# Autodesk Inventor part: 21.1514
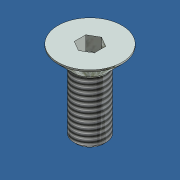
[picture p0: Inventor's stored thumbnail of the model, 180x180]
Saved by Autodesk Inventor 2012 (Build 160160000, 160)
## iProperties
Created: 2006-12
Part Number: 21.1514
Material: Steel, Mild
Description: M8x20 C'SUNK
Document SubType Name: Modeling
Standard: DIN 7991
Designer: Andy Moles
Standards Organization: DIN
Language: en-US
Size Designation: M8x20
Categories: <MemberInstance Version="R10.0.0"><Categories><Category DisplayName="Fasteners" InternalName="e4da775c-781d-43d5-af7c-5136215cf5a6" Mnemonic="FSTN"><Category Di
Density: 7.86 g/cm^3
Mass: 9.85186 g
Surface Area: 9.27162 cm^2
Volume: 1.25342 cm^3
Vendor: S
Author: Andy Moles
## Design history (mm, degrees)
node "Sketch1"
node "WorkPoint1"
sketch "Sketch2"
  geometry: L1 (-4, -20)-(0, -20); L2 (-4, -4.4)-(-4, -20); L3 (-8, -0.4)-(-4, -4.4); L4 (-8, 0)-(-8, -0.4); L5 (0, 0)-(-8, 0); L6 (0, -20)-(0, 0); L7 (0, -20)-(0, 0); L8 (0, -22)-(0, 6) reference; L9 (0.8, 0)-(-10.4, 0) reference
  constraints: 14 end point, 3 vertical, 2 horizontal
  dimensions: "d1" = 45 deg angle of L3 L6; "d3" = 8 distance of L5.start L4.start (= 0.5 x dk); "d5" = 4 distance of L1.start L1.end (= 0.5 x NND); "d7" = 20 distance of L1.end L5.start (= NLG); "ParC" = 0.4 distance of L4.start L3.start; "d22" = 0 distance between parallel lines of L8 L6; "d23" = 0 distance between parallel lines of L9 L5
fillet "Fillet1" dims "d18" = 0.5 (= r)
chamfer "Chamfer1" distance "d19" = 0.625 (= 0.5 x PTC); stored, may be unused: angle "d20" = 45 deg, second distance "d39" = 0.625 (= 0.5 x PTC)
node "MSC_A1"
node "MSC_PF1"
node "MSC_PT1"
body "Solid1"
revolve "Revolution1" stored, may be unused: angle "d8" = 360 deg
sketch "Sketch3"
  geometry: L1 (-2.5, 1.443)-(-2.5, -1.443); L2 (0, 2.887)-(-2.5, 1.443); L3 (2.5, 1.443)-(0, 2.887); L4 (2.5, -1.443)-(2.5, 1.443); L5 (0, -2.887)-(2.5, -1.443); L6 (-2.5, -1.443)-(0, -2.887); C1 r 2.5 at (0, 0); C2 r 4 at (0, 0) reference
  constraints: 12 end point, 6 tangent, 2 parallel, 2 vertical, 1 centre point, 1 concentric
  dimensions: "d11" = 5 diameter of C1 (= ParS); "d13" = 120 deg angle of L1 L2; "d15" = 120 deg angle of L6 L1
extrude "Extrusion1" cut sketch "Sketch3" distance "d16" = 3.5 (= ParT); taper "d17" = 0 deg
thread "Thread1" dims "d35" = 0, "b" = 16
other parameters: "NND" = 8 [user parameter; used in 2 equation terms], "PTC" = 1.25 [user parameter; used in 2 equation terms], "dk" = 16 [user parameter; used in 1 equation term], "ParK" = 4.4 [user parameter], "ParS" = 5 [user parameter; used in 1 equation term], "ParT" = 3.5 [user parameter; used in 1 equation term], "r" = 0.5 [user parameter; used in 1 equation term], "NLG" = 20 [user parameter; used in 1 equation term], "d0" = 45 deg (derived), "d2" = 3 (derived), "d4" = 1.5 (derived), "d6" = 8 (derived), "d9" = 0, "d10" = 2 (derived), "d12" = 120 deg (derived), "d14" = 120 deg (derived), "d37" = 0, "d38" = 0, "d40" = 0, "d41" = 0, "d42" = 0, "THREADDIA" = 8 (= NND) [user parameter]
